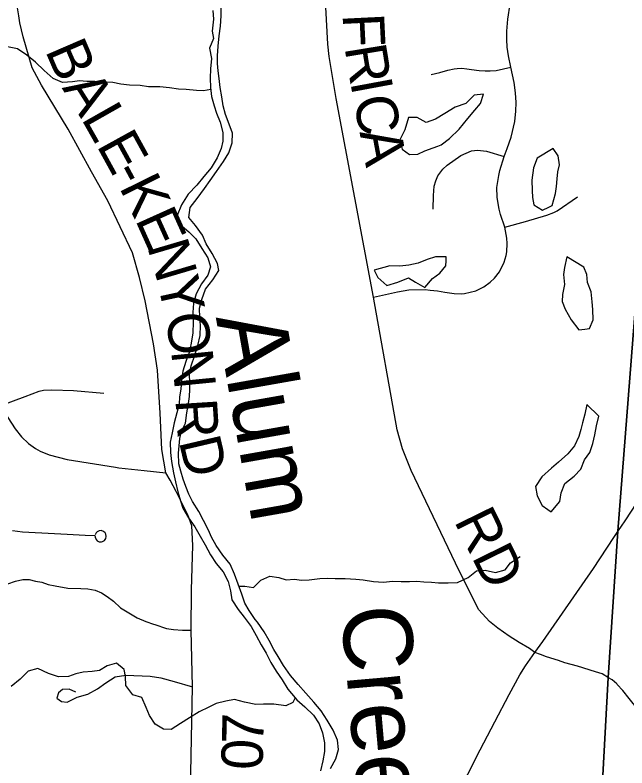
# Model space of a CAD drawing. Extents: x 0 to 34, y 0 to 22.
# Drawn here: x 7.091 to 7.93, y 8.523 to 9.554 of the extents above; entities that cross this region are included whole.
import ezdxf

# ---------------------------------------------------------------- set-up
doc = ezdxf.new("R2010")
doc.units = 0
for name, color, linetype in [('GM_X_Corporation', 7, 'Continuous'), ('GM_X_County_Road', 7, 'Continuous'), ('GM_X_County_Road_Text', 7, 'Continuous'), ('GM_X_Major_River', 7, 'Continuous'), ('GM_X_Minor_Lake', 7, 'Continuous'), ('GM_X_Minor_River', 7, 'Continuous'), ('GM_X_Minor_River_Text', 7, 'Continuous'), ('GM_X_Township_Road', 7, 'Continuous'), ('GM_X_Township_Road_Text', 7, 'Continuous')]:
    doc.layers.add(name, color=color, linetype=linetype)

msp = doc.modelspace()

# ---------------------------------------------------------------- linework, layer by layer
at = {"layer": 'GM_X_Corporation'}
for points in [[(7.8118, 7.1421), (7.8248, 7.359), (7.8619, 7.9568), (7.8769, 8.1664), (7.8824, 8.2446), (7.9043, 8.6471), (7.9173, 8.8475), (7.9854, 9.7171), (7.9906, 9.8037), (8.012, 10.1113), (8.0168, 10.1841), (3.5182, 10.1841)], [(10.3182, 6.9963), (10.3182, 10.1841), (8.0168, 10.1841), (8.012, 10.1113), (7.9906, 9.8037), (7.9854, 9.7171), (7.9173, 8.8475), (7.9043, 8.6471), (7.8824, 8.2446), (7.8769, 8.1664), (7.8619, 7.9568), (7.8248, 7.359), (7.8118, 7.1421)]]:
    msp.add_lwpolyline(points, dxfattribs=at)
at = {"layer": 'GM_X_County_Road'}
for points in [[(7.912, 8.8386), (7.9175, 8.8469), (7.9273, 8.8617), (7.9519, 8.8986), (7.9823, 8.9444), (8.01, 8.9865), (8.0467, 9.0401), (8.1152, 9.1411), (8.1602, 9.2081), (8.1982, 9.2649), (8.2124, 9.2864), (8.2386, 9.3265), (8.2701, 9.3735), (8.3583, 9.503), (8.3891, 9.5483), (8.4326, 9.6127), (8.4704, 9.6727), (8.4896, 9.704), (8.5044, 9.7253), (8.5147, 9.7403), (8.5806, 9.8369), (8.6158, 9.8872), (8.7218, 10.048), (8.8088, 10.1841)], [(7.8038, 8.6814), (7.7964, 8.6866), (7.7824, 8.695), (7.7684, 8.7036), (7.7528, 8.7145), (7.7418, 8.7239), (7.7271, 8.7399), (7.7002, 8.793), (7.6343, 8.9304), (7.6223, 8.96), (7.6151, 8.9864), (7.5828, 9.1679), (7.5314, 9.44), (7.5217, 9.4977), (7.52, 9.5144), (7.5175, 9.5651)], [(7.729, 8.5478), (7.7489, 8.5863), (7.7686, 8.6235), (7.7831, 8.6505), (7.791, 8.6631), (7.8038, 8.6814), (7.8146, 8.6965), (7.8841, 8.7963), (7.912, 8.8386)], [(7.9166, 8.6375), (7.9159, 8.6382), (7.9096, 8.6437), (7.9045, 8.6466), (7.8961, 8.6518), (7.8869, 8.6547), (7.862, 8.6624), (7.8447, 8.6673), (7.8361, 8.6701), (7.8199, 8.6754), (7.8115, 8.6783), (7.8038, 8.6814)], [(8.2228, 8.2286), (8.206, 8.2511), (8.1701, 8.2992), (8.1419, 8.3375), (8.1248, 8.3616), (8.1056, 8.3853), (8.0786, 8.4211), (8.0525, 8.4555), (8.0185, 8.504), (7.9838, 8.5516), (7.9559, 8.5901), (7.9329, 8.6182), (7.9244, 8.6291), (7.9166, 8.6375)], [(7.652, 8.3987), (7.6742, 8.4428), (7.6921, 8.4775), (7.7118, 8.5147), (7.729, 8.5478)]]:
    msp.add_lwpolyline(points, dxfattribs=at)
at = {"layer": 'GM_X_Major_River'}
for points in [[(7.4203, 8.7265), (7.4121, 8.7387), (7.4065, 8.7486), (7.4024, 8.7611), (7.3972, 8.7748), (7.3923, 8.7885), (7.386, 8.8022), (7.3762, 8.8144), (7.3669, 8.8277), (7.3605, 8.8391), (7.3564, 8.849), (7.3497, 8.8619), (7.3433, 8.8745), (7.3347, 8.8881), (7.3298, 8.898), (7.3254, 8.9087), (7.3216, 8.9186), (7.3187, 8.9296), (7.3161, 8.9394), (7.3154, 8.9542), (7.3162, 8.9645), (7.3174, 8.9743), (7.3194, 8.9845), (7.3251, 8.9955), (7.3267, 9.0095), (7.3291, 9.0224), (7.3307, 9.0319), (7.3311, 9.0413), (7.3308, 9.0512), (7.3305, 9.0618), (7.3328, 9.0739), (7.3378, 9.0883), (7.3417, 9.1016), (7.3452, 9.1152), (7.3456, 9.1289), (7.3446, 9.1402), (7.3443, 9.1527), (7.3474, 9.1649), (7.3524, 9.1789), (7.3627, 9.1917), (7.3707, 9.2045), (7.3688, 9.214), (7.3614, 9.2277), (7.3535, 9.2407), (7.3483, 9.2528), (7.3389, 9.2661), (7.3295, 9.2768), (7.3315, 9.2908), (7.341, 9.3029), (7.3509, 9.3165), (7.3586, 9.3275), (7.3673, 9.3399), (7.3773, 9.3535), (7.3845, 9.3656), (7.3891, 9.3792), (7.3892, 9.3925), (7.3848, 9.405), (7.3799, 9.4179), (7.3766, 9.4301), (7.3748, 9.4422), (7.3726, 9.4551), (7.3711, 9.4673), (7.3697, 9.4779), (7.369, 9.4881), (7.3687, 9.4984), (7.3699, 9.5116), (7.3711, 9.5257), (7.3731, 9.5389), (7.3739, 9.5533), (7.3741, 9.573)], [(7.3623, 9.5606), (7.3633, 9.5485), (7.3614, 9.532), (7.3632, 9.5223), (7.3578, 9.5087), (7.3607, 9.4946), (7.3591, 9.4806), (7.3587, 9.4677), (7.3593, 9.4552), (7.3608, 9.4427), (7.3641, 9.4298), (7.3674, 9.4199), (7.3727, 9.4074), (7.376, 9.3933), (7.3763, 9.3816), (7.374, 9.3717), (7.3686, 9.3585), (7.3602, 9.3449), (7.3503, 9.3332), (7.3407, 9.3211), (7.3286, 9.309), (7.3194, 9.2943), (7.3136, 9.2799), (7.3177, 9.2674), (7.3294, 9.2575), (7.3392, 9.2476), (7.3474, 9.2346), (7.3556, 9.2217), (7.3594, 9.2092), (7.3555, 9.1978), (7.3471, 9.1861), (7.3398, 9.1725), (7.336, 9.1596), (7.3351, 9.1467), (7.3354, 9.1335), (7.335, 9.1191), (7.3326, 9.1047), (7.3299, 9.0922), (7.3253, 9.0797), (7.3214, 9.0664), (7.3194, 9.0539), (7.3186, 9.0418), (7.317, 9.0312), (7.3162, 9.0213), (7.3131, 9.0096), (7.3096, 8.996), (7.3069, 8.9823), (7.3042, 8.9691), (7.3045, 8.955), (7.3059, 8.9429), (7.3088, 8.9273), (7.3114, 8.9152), (7.3147, 8.9015), (7.3181, 8.889), (7.3214, 8.8791), (7.3293, 8.8658), (7.3379, 8.8533), (7.345, 8.8407), (7.3521, 8.8289), (7.3592, 8.8148), (7.3671, 8.803), (7.3765, 8.7916), (7.3836, 8.7787), (7.3869, 8.7658), (7.3884, 8.7533), (7.397, 8.7403), (7.4056, 8.7297), (7.415, 8.7167), (7.4217, 8.7045), (7.4288, 8.6916), (7.4356, 8.6802), (7.4419, 8.6677), (7.4494, 8.6555), (7.4573, 8.6437), (7.4652, 8.6311), (7.4753, 8.6193)], [(7.5235, 8.5224), (7.5312, 8.5356), (7.5347, 8.5485), (7.5332, 8.561), (7.5272, 8.5747), (7.519, 8.5884), (7.5108, 8.6013), (7.501, 8.6131), (7.4901, 8.6257), (7.4796, 8.6375), (7.4691, 8.6497), (7.4593, 8.6634), (7.4522, 8.6759), (7.4462, 8.6854), (7.4395, 8.6976), (7.4327, 8.7094), (7.4237, 8.7227), (7.4203, 8.7265)], [(7.4753, 8.6193), (7.4776, 8.6163), (7.4885, 8.6067), (7.5005, 8.5953), (7.5084, 8.5835), (7.5128, 8.571), (7.5154, 8.5573), (7.5153, 8.5455), (7.513, 8.5327), (7.5099, 8.5194)]]:
    msp.add_lwpolyline(points, dxfattribs=at)
at = {"layer": 'GM_X_Minor_Lake'}
for points in [[(7.6707, 9.3748), (7.6753, 9.3767), (7.6867, 9.3851), (7.6999, 9.398), (7.712, 9.4124), (7.7214, 9.4238), (7.7294, 9.4333), (7.7335, 9.4458), (7.7207, 9.4443), (7.7093, 9.4333), (7.6946, 9.4283), (7.6806, 9.4192), (7.6677, 9.4116), (7.6549, 9.407), (7.6424, 9.4138), (7.6306, 9.4138)], [(7.6306, 9.4138), (7.6254, 9.3971), (7.6186, 9.3835), (7.622, 9.3706), (7.6318, 9.3634), (7.6432, 9.3638), (7.653, 9.3684), (7.6644, 9.3722), (7.6707, 9.3748)], [(7.829, 9.3713), (7.807, 9.3583), (7.8021, 9.3451), (7.7995, 9.328), (7.7999, 9.314), (7.8006, 9.3045), (7.8022, 9.2943), (7.8143, 9.2871), (7.8228, 9.2913)], [(7.8228, 9.2913), (7.8275, 9.2935), (7.832, 9.3099), (7.8332, 9.3193), (7.8343, 9.3299), (7.8354, 9.3394), (7.8373, 9.3493), (7.8358, 9.3614), (7.829, 9.3713)], [(7.6821, 9.2178), (7.6823, 9.2232), (7.6675, 9.2232), (7.6562, 9.2194), (7.6437, 9.2144), (7.6312, 9.2118), (7.6187, 9.2102), (7.6051, 9.2106), (7.5836, 9.2049)], [(7.8476, 9.2231), (7.8443, 9.2083), (7.8431, 9.1988), (7.8443, 9.1851), (7.8416, 9.1715), (7.8413, 9.162), (7.8451, 9.1514), (7.8534, 9.137), (7.864, 9.123), (7.8721, 9.1241)], [(7.8721, 9.1241), (7.8784, 9.1249), (7.8837, 9.1367), (7.8833, 9.1511), (7.8821, 9.1617), (7.881, 9.175), (7.8757, 9.1878), (7.8749, 9.1988), (7.8707, 9.2091), (7.8476, 9.2231)], [(7.5836, 9.2049), (7.5885, 9.195), (7.601, 9.184), (7.6161, 9.1882), (7.6305, 9.1943), (7.6403, 9.1886), (7.6528, 9.1811), (7.6634, 9.1936), (7.6736, 9.2008), (7.6819, 9.2107), (7.6821, 9.2178)], [(7.8751, 9.021), (7.8721, 9.0077), (7.8691, 8.996), (7.8668, 8.9865), (7.8642, 8.977), (7.8581, 8.9645), (7.8487, 8.9531), (7.8362, 8.9421), (7.8264, 8.9338), (7.8132, 8.9216), (7.8045, 8.9087), (7.8071, 8.8958), (7.8136, 8.8826), (7.8213, 8.8772)], [(7.8213, 8.8772), (7.8261, 8.8739), (7.8378, 8.8879), (7.8397, 8.8997), (7.845, 8.9125), (7.8574, 8.9228), (7.8669, 8.9323), (7.8718, 8.9452), (7.879, 8.9551), (7.8831, 8.9676), (7.8857, 8.9793), (7.8884, 8.9918), (7.8914, 9.0051), (7.8751, 9.021)]]:
    msp.add_lwpolyline(points, dxfattribs=at)
at = {"layer": 'GM_X_Minor_River'}
for points in [[(7.3597, 9.4521), (7.3498, 9.4506), (7.34, 9.4509), (7.326, 9.4524), (7.3154, 9.4528), (7.3033, 9.4547), (7.2897, 9.4558), (7.2745, 9.4561), (7.2628, 9.4576), (7.2484, 9.4584), (7.2363, 9.4595), (7.2253, 9.4621), (7.211, 9.4625), (7.2007, 9.4632), (7.1898, 9.4632), (7.1799, 9.464), (7.1701, 9.4628), (7.1565, 9.462), (7.1436, 9.4673), (7.1315, 9.4783), (7.1194, 9.4897), (7.1076, 9.4995), (7.0947, 9.5078), (7.0811, 9.5108)], [(7.3982, 8.7722), (7.4062, 8.772), (7.4183, 8.7701), (7.4281, 8.7804), (7.4406, 8.7857), (7.4527, 8.7838), (7.4629, 8.7808), (7.4743, 8.7816), (7.4841, 8.7801), (7.4943, 8.7809), (7.5091, 8.7828), (7.5193, 8.7832), (7.5303, 8.7828), (7.5439, 8.7825), (7.5583, 8.7817), (7.5685, 8.7806), (7.5825, 8.7783), (7.5965, 8.7776), (7.6086, 8.7791), (7.6207, 8.7784), (7.6321, 8.7784), (7.6419, 8.7788), (7.6517, 8.7781), (7.662, 8.7777), (7.6718, 8.7766), (7.685, 8.7766), (7.6979, 8.777), (7.7123, 8.7838), (7.7236, 8.793), (7.7357, 8.7941), (7.7497, 8.7907), (7.763, 8.7945), (7.7705, 8.804), (7.7834, 8.8128)], [(7.4753, 8.6193), (7.4719, 8.6128), (7.4627, 8.6083), (7.4461, 8.6106), (7.4317, 8.6105), (7.4215, 8.6102), (7.406, 8.6132), (7.392, 8.6169), (7.3802, 8.6146), (7.367, 8.6116), (7.3568, 8.6066), (7.3436, 8.6002), (7.3303, 8.5918), (7.3182, 8.5842), (7.3054, 8.5759), (7.2951, 8.5762), (7.2834, 8.583), (7.2758, 8.5948), (7.2709, 8.6061), (7.2652, 8.6194), (7.2527, 8.6232), (7.2432, 8.636), (7.2429, 8.6486), (7.2409, 8.658), (7.2303, 8.6667), (7.2175, 8.6629), (7.2073, 8.6568), (7.1971, 8.6553), (7.185, 8.6542), (7.1747, 8.6519), (7.1649, 8.6484), (7.1509, 8.6477), (7.1373, 8.6526), (7.1225, 8.6594), (7.1096, 8.6556), (7.0987, 8.6445), (7.0862, 8.6347)]]:
    msp.add_lwpolyline(points, dxfattribs=at)
at = {"layer": 'GM_X_Township_Road'}
msp.add_line((7.2685, 8.9305), (7.2982, 8.9273), dxfattribs=at)
for points in [[(7.0965, 9.5534), (7.0934, 9.5722), (7.0887, 9.5964), (7.0817, 9.6255), (7.0636, 9.6763), (7.0564, 9.6902), (7.0442, 9.7481), (7.0366, 9.7911), (7.0349, 9.8181)], [(7.6605, 9.1776), (7.6705, 9.1767), (7.6804, 9.1746), (7.6933, 9.1727), (7.7027, 9.1725), (7.7074, 9.1729), (7.7228, 9.1765), (7.7336, 9.1819), (7.7423, 9.1885), (7.7486, 9.1941), (7.7551, 9.2028), (7.7619, 9.216), (7.7645, 9.225), (7.7654, 9.2299), (7.7657, 9.2413), (7.7652, 9.2487), (7.7624, 9.2636), (7.7566, 9.2812), (7.7548, 9.2884), (7.7537, 9.2935), (7.7521, 9.3049), (7.7518, 9.3181), (7.7542, 9.3345), (7.7559, 9.3414), (7.7618, 9.3606), (7.7658, 9.3716), (7.7711, 9.3868), (7.7763, 9.4085), (7.7778, 9.4228), (7.7781, 9.4346), (7.7774, 9.4479), (7.7755, 9.4618), (7.7706, 9.4827), (7.7675, 9.4984), (7.766, 9.5101), (7.7653, 9.5206), (7.7652, 9.5323), (7.7669, 9.5484), (7.77, 9.5697)], [(7.3317, 8.4929), (7.3345, 8.6341), (7.3328, 8.7119), (7.3332, 8.7671), (7.3349, 8.8276), (7.3335, 8.8547), (7.3282, 8.8699), (7.3124, 8.9016), (7.3041, 8.9171), (7.2982, 8.9273), (7.2928, 8.9591), (7.2901, 9.0088), (7.2866, 9.0679), (7.281, 9.1039), (7.2697, 9.163), (7.2621, 9.1948), (7.2522, 9.2286), (7.2186, 9.2997), (7.1963, 9.3397), (7.1643, 9.3981), (7.1275, 9.458), (7.1147, 9.482), (7.1027, 9.5244), (7.0981, 9.5435), (7.0965, 9.5534)], [(7.6615, 9.4727), (7.6737, 9.4757), (7.6844, 9.4786), (7.6932, 9.4807), (7.6973, 9.4811), (7.7038, 9.4813), (7.7103, 9.4806), (7.7168, 9.4797), (7.7276, 9.4781), (7.7358, 9.4777), (7.7426, 9.4779), (7.7508, 9.4785), (7.7706, 9.4827)], [(7.6645, 9.2886), (7.6648, 9.3072), (7.6658, 9.3198), (7.6679, 9.3272), (7.671, 9.3341), (7.6777, 9.3434), (7.6836, 9.3486), (7.7023, 9.3617), (7.7167, 9.3681), (7.7251, 9.3691), (7.7374, 9.3679), (7.7618, 9.3606)], [(7.7624, 9.2636), (7.7908, 9.2715), (7.8203, 9.28), (7.8296, 9.2837), (7.8341, 9.2863), (7.8622, 9.3055)], [(7.5828, 9.1679), (7.6154, 9.175), (7.6312, 9.178), (7.6536, 9.1783), (7.6605, 9.1776)], [(7.0654, 9.0877), (7.065, 9.0656), (7.0653, 9.056), (7.0665, 9.0448), (7.0712, 9.0266), (7.0735, 9.0201), (7.0815, 9.0032), (7.0916, 8.9876), (7.1004, 8.9767), (7.1101, 8.9676), (7.1196, 8.9608), (7.1257, 8.9572), (7.138, 8.9518), (7.163, 8.9454), (7.229, 8.9351)], [(7.0735, 9.0201), (7.1051, 9.0319), (7.1245, 9.0391), (7.1304, 9.0404), (7.1418, 9.0411), (7.1714, 9.0399), (7.2133, 9.0366)], [(7.229, 8.9351), (7.2339, 8.9343), (7.2685, 8.9305)], [(7.0879, 8.8481), (7.1017, 8.8466), (7.1457, 8.8442), (7.1629, 8.8431), (7.1876, 8.8419)], [(7.1876, 8.8419), (7.2009, 8.8413), (7.2011, 8.8392), (7.2024, 8.836), (7.2039, 8.8341), (7.2067, 8.8329), (7.2098, 8.8328), (7.2113, 8.8332), (7.2139, 8.8348), (7.2157, 8.8373), (7.2164, 8.8403), (7.2159, 8.8433), (7.2149, 8.8452), (7.2126, 8.8471), (7.2096, 8.8481), (7.2065, 8.8478), (7.2038, 8.8464), (7.2027, 8.8453), (7.2012, 8.8426)], [(7.0817, 8.7752), (7.0921, 8.7791), (7.1019, 8.781), (7.1108, 8.781), (7.1195, 8.7791), (7.1282, 8.7774), (7.1368, 8.7743), (7.1466, 8.7724), (7.164, 8.7693), (7.1816, 8.769), (7.1912, 8.7685), (7.2014, 8.7666), (7.2097, 8.763), (7.2175, 8.7579), (7.2265, 8.7515), (7.2358, 8.7424), (7.2473, 8.7355), (7.2588, 8.7287), (7.2705, 8.7236), (7.2811, 8.72), (7.283, 8.7194)], [(7.283, 8.7194), (7.299, 8.714), (7.3088, 8.7128), (7.3209, 8.7117), (7.3328, 8.7119)], [(7.1748, 8.6268), (7.1657, 8.631), (7.1565, 8.6306), (7.1512, 8.626), (7.1485, 8.6187), (7.155, 8.6142), (7.163, 8.6134), (7.1768, 8.6199), (7.1913, 8.6241), (7.2046, 8.6317), (7.2157, 8.6397), (7.2287, 8.6478), (7.2432, 8.6501), (7.2764, 8.6489), (7.2913, 8.6466), (7.3096, 8.6417), (7.3345, 8.6341)]]:
    msp.add_lwpolyline(points, dxfattribs=at)

# ---------------------------------------------------------------- texts
at = {"layer": 'GM_X_County_Road_Text'}
for s, height, rotation, p in [('F', 0.0568, 272.8584, (7.5402, 9.5554)), ('R', 0.0568, 279.2957, (7.5428, 9.5102)), ('I', 0.0568, 280.536, (7.5506, 9.4628)), ('C', 0.0568, 280.5188, (7.5549, 9.4399)), ('A', 0.0568, 280.5206, (7.5634, 9.394)), ('RD', 0.05682, 296.1299, (7.6924, 8.8617))]:
    msp.add_text(s, height=height, rotation=rotation, dxfattribs=at).set_placement(p)
at = {"layer": 'GM_X_Minor_River_Text'}
for s, rotation, p in [('Alum', 280.0053, (7.3665, 9.1403)), ('Creek', 275.0046, (7.5377, 8.7424))]:
    msp.add_text(s, height=0.09469, rotation=rotation, dxfattribs=at).set_placement(p)
at = {"layer": 'GM_X_Township_Road_Text'}
for s, rotation, p in [('B', 293.3526, (7.1322, 9.5058)), ('A', 302.2316, (7.1552, 9.4544)), ('L', 299.5131, (7.1815, 9.4127)), ('E', 298.8348, (7.2024, 9.3759)), ('-', 298.2672, (7.2228, 9.3388)), ('K', 296.2238, (7.2336, 9.3187)), ('E', 294.2358, (7.2555, 9.2744)), ('N', 286.4728, (7.2722, 9.2375)), ('Y', 282.1783, (7.2861, 9.1907)), ('O', 280.2247, (7.2966, 9.1423)), ('N', 275.6153, (7.3053, 9.0943)), ('R', 273.5774, (7.3112, 9.0276)), ('D', 283.2276, (7.3157, 8.9707)), ('7', 88.5622, (7.4315, 8.5552)), ('0', 88.3481, (7.4305, 8.5199))]:
    msp.add_text(s, height=0.0568, rotation=rotation, dxfattribs=at).set_placement(p)

doc.saveas('drawing.dxf')
